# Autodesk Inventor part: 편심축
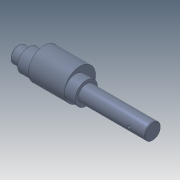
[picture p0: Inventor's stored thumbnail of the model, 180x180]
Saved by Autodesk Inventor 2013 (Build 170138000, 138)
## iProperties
Manager: 한국ATC센터
Company: 한국ATC센터
Created: 2014-07
Part Number: 편심축
Document SubType Name: Modeling
Designer: KYOUNG IL JANG
Density: 7.86 g/cm^3
Material: 강, 연강
Mass: 1544.74 g
Surface Area: 256.354 cm^2
Volume: 196.531 cm^3
Author: KYOUNG IL JANG
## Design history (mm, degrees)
sketch "스케치1"
  geometry: L1 (-105, 0)-(105, 0); L2 (-105, 0)-(-105, 12.5); L3 (-105, 12.5)-(-89, 12.5); L4 (-89, 12.5)-(-89, 17.5); L5 (-89, 17.5)-(-82, 17.5); L6 (-82, 17.5)-(-82, 12.5); L7 (-82, 12.5)-(-0.35, 12.5); L8 (-0.35, 12.5)-(-0.35, 11.95); L9 (-0.35, 11.95)-(1, 11.95); L10 (1, 11.95)-(1, 12.5); L11 (1, 12.5)-(105, 12.5); L12 (105, 12.5)-(105, 0); L13 (70, 12.5)-(70, 9.1); L14 (70, 9.1)-(95, 9.1); L15 (95, 9.1)-(95, 12.5); L16 (80, -12.5)-(82.5, -12.5); L17 (82.5, -12.5)-(80, -10); L18 (80, -10)-(80, -12.5); L19 (1, 12.5)-(-0.35, 12.5); 2 further points
  constraints: 38 end point, 8 parallel, 5 collinear, 5 perpendicular, 2 point on line, 1 coincident, 1 horizontal, 1 midpoint, 1 vertical
  dimensions: "d0" = 210 distance of L1.start L1.end; "d1" = 25 diameter of L3 L1; "d2" = 35 diameter of L5 L1; "d3" = 16 distance of L2.end L3.end; "d6" = 1.35 distance of L8.end L9.end; "d7" = 23.9 diameter of L9 L1; "d8" = 3.4 distance between parallel lines of L14 L11; "d9" = 10 distance between parallel lines of L15 L12; "d10" = 25 distance of L13.end L14.end; "d11" = 25 diameter of L16 L1 (= d1); "d12" = 25 distance from line of L12 L16.start; "d13" = 45 deg angle of L17 L18; "d14" = 5 diameter of L16.end L18; "d27" = 104 distance between parallel lines of L10 L12; "d35" = 7 distance of L4.end L5.end
revolve "회전1" stored, may be unused: angle "d15" = 90 deg
revolve "회전2" stored, may be unused: angle "d16" = 90 deg
extrude "돌출1" cut sketch "스케치1" stored distance "d17" = 8; taper "d18" = 0 deg
fillet "모깎기1" dims "d19" = 4
node "작업 평면1"
sketch "스케치2"
  geometry: C1 r 12.5 at (0, 0) reference; C2 r 17.5 at (0, 0); C3 r 24.5 at (0, 7); 1 further point
  constraints: 2 centre point, 1 coincident, 1 tangent, 1 vertical alignment
  dimensions: "d32" = 35 diameter of C2; "d33" = 49 diameter of C3 (derived); "d34" = 7 distance of C3.centre point (0, 0)
extrude "돌출2" join sketch "스케치2" distance "d22" = 56; taper "d23" = 0 deg
chamfer "모따기1" distance "d24" = 1; stored, may be unused: second distance "d25" = 2, angle "d26" = 45 deg
feature "면 이동1" dims "d31" = 83
node "솔리드1"
